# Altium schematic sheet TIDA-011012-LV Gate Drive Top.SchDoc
size 431 x 279 mm; Date: Not shown in title block; ApprovedBy: Not shown in title block; CheckedBy: Not shown in title block; Author: Not shown in title block; CompanyName: Not shown in title block; Engineer: Not shown in title block; Organization: Not shown in title block; Address1: Not shown in title block; Address2: Not shown in title block; Address3: Not shown in title block; Address4: Not shown in title block; DocumentNumber: 1; Revision: Use project parameter SCH_Rev; SheetNumber: 1; SheetTotal: 1; PageSetup: Record=PageOptions¦CenterHorizontal=True¦CenterVertical=True¦PrintScale=1.00¦XCorrection=1.00¦YCorrection=1.00¦PrintKind=0¦BorderSize=5000000¦LeftOffset=0¦BottomOffset=0¦Orientation=2¦PaperLength=1000¦PaperWidth=1000¦Scale=100¦PaperSource=15¦PrintQuality=600¦MediaType=1¦DitherType=10¦PaperKind=Letter¦PrintScaleMode=1
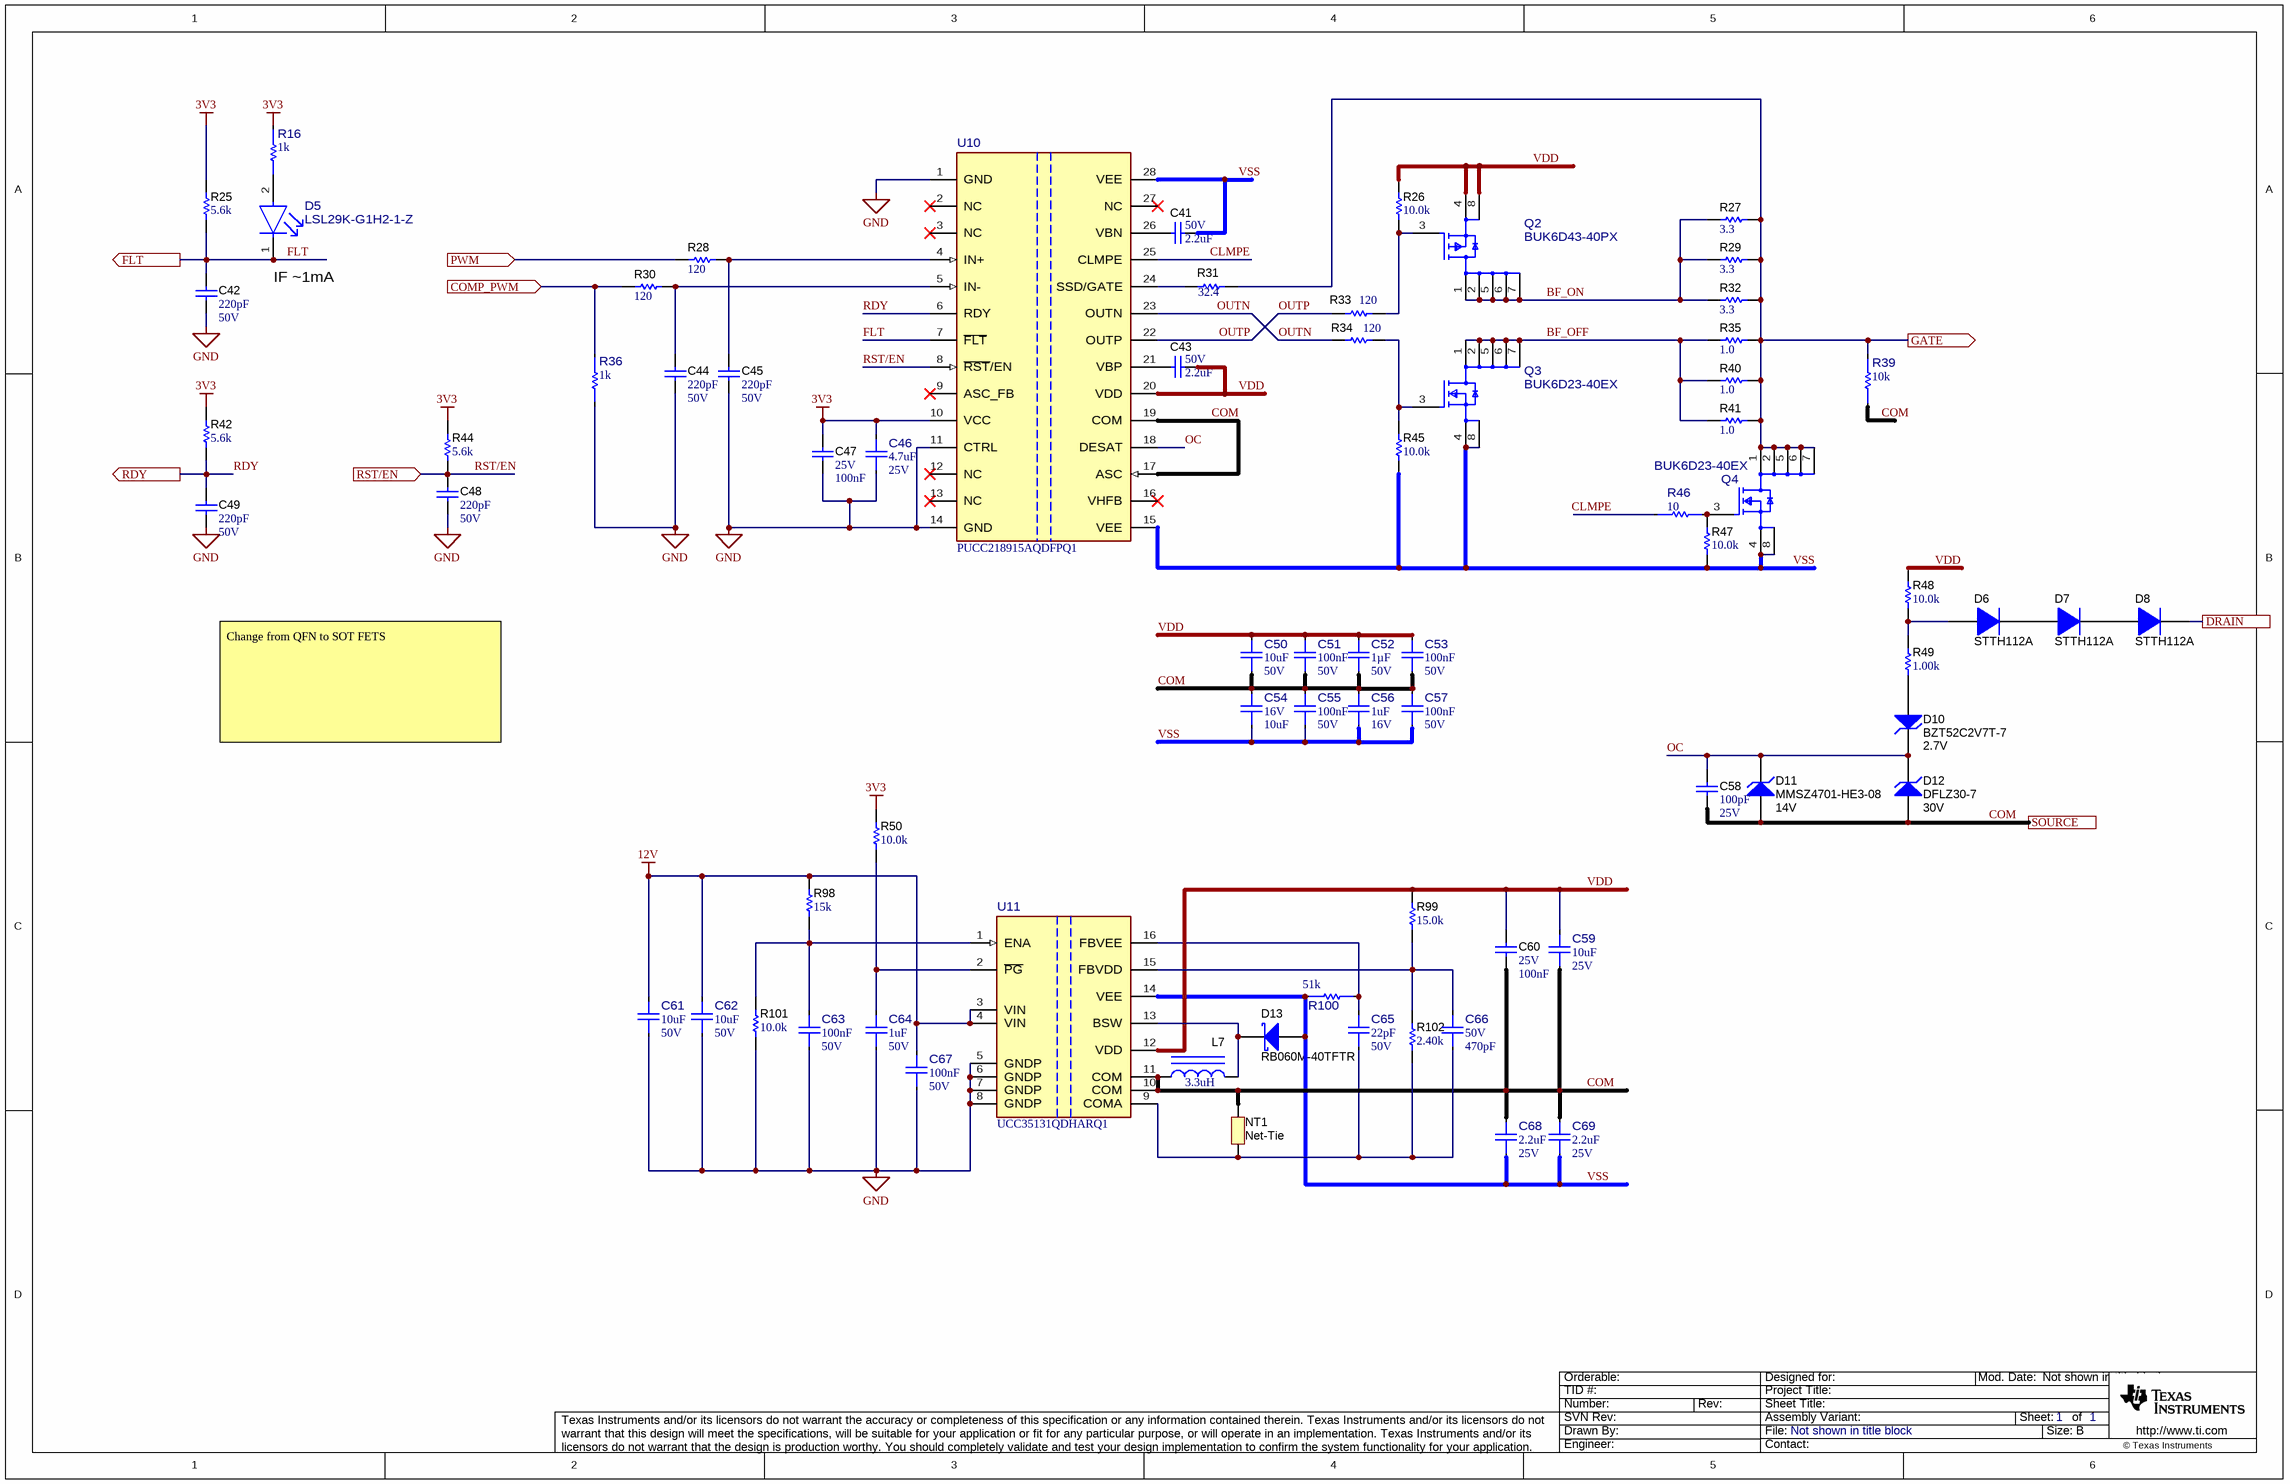
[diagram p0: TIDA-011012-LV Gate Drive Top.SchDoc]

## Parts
C41  VDC_V: 50V  ValueDisplayed: 2.2uF  [0603]  (hidden comment: GRT188R61H225KE13D)
C42  Cap_F: 220pF  VDC_V: 50V  [0603]  (hidden comment: C0603C221K5RACTU)
C43  VDC_V: 50V  ValueDisplayed: 2.2uF  [0603]  (hidden comment: GRT188R61H225KE13D)
C44  Cap_F: 220pF  VDC_V: 50V  [0603]  (hidden comment: C0603C221K5RACTU)
C45  Cap_F: 220pF  VDC_V: 50V  [0603]  (hidden comment: C0603C221K5RACTU)
C46  ValueDisplayed: 4.7uF  VDC_V: 25V  [FP-GRM188R61E475KE15D_0603-MFG]  (hidden comment: GRM188R61E475KE15D)
C47  VDC_V: 25V  Cap_F: 100nF  [0603]  (hidden comment: GCM188R71E104KA57D)
C48  Cap_F: 220pF  VDC_V: 50V  [0603]  (hidden comment: C0603C221K5RACTU)
C49  Cap_F: 220pF  VDC_V: 50V  [0603]  (hidden comment: C0603C221K5RACTU)
C50  ValueDisplayed: 10uF  VDC_V: 50V  [FP-GMC31X7R106K50NT_1206-MFG]  (hidden comment: GMC31X7R106K50NT)
C51  Cap_F: 100nF  VDC_V: 50V  [FP-C0805C104K5RAC7800_0805-MFG]  (hidden comment: C0805C104K5RAC7800)
C52  Cap_F: 1µF  VDC_V: 50V  [FP-CL10B105KB9VPJC_0603-MFG]  (hidden comment: CL10B105KB9VPJC)
C53  Cap_F: 100nF  VDC_V: 50V  [FP-C0603C104K5RAC3121_0603-MFG]  (hidden comment: C0603C104K5RAC3121)
C54  VDC_V: 16V  ValueDisplayed: 10uF  [FP-C1206C106J4RACAUTO_1206-MFG]  (hidden comment: C1206C106J4RACAUTO)
C55  Cap_F: 100nF  VDC_V: 50V  [FP-C0805C104K5RAC7800_0805-MFG]  (hidden comment: C0805C104K5RAC7800)
C56  ValueDisplayed: 1uF  VDC_V: 16V  [FP-GRM188C71C105KA12D_0603-MFG]  (hidden comment: GRM188C71C105KA12D)
C57  Cap_F: 100nF  VDC_V: 50V  [FP-C0603C104K5RAC3121_0603-MFG]  (hidden comment: C0603C104K5RAC3121)
C58  Cap_F: 100pF  VDC_V: 25V  [0603]  (hidden comment: 06033C101KAT2A)
C59  ValueDisplayed: 10uF  VDC_V: 25V  [FP-KGM31HR71E106KU_1206-MFG]  (hidden comment: KGM31HR71E106KU)
C60  VDC_V: 25V  Cap_F: 100nF  [0603]  (hidden comment: GCM188R71E104KA57D)
C61  ValueDisplayed: 10uF  VDC_V: 50V  [FP-GMC31X7R106K50NT_1206-MFG]  (hidden comment: GMC31X7R106K50NT)
C62  ValueDisplayed: 10uF  VDC_V: 50V  [FP-GMC31X7R106K50NT_1206-MFG]  (hidden comment: GMC31X7R106K50NT)
C63  Cap_F: 100nF  VDC_V: 50V  [FP-KGM15BR71H104JT_0603-MFG]  (hidden comment: KGM15BR71H104JT)
C64  ValueDisplayed: 1uF  VDC_V: 50V  [FP-C1206C105J5RECAUTO_1206-MFG]  (hidden comment: C1206C105J5RECAUTO)
C65  ValueDisplayed: 22pF  VDC_V: 50V  [FP-VJ0603D220JLAAJ32_0603-IPC_C]  (hidden comment: VJ0603D220JLAAJ32)
C66  VDC_V: 50V  ValueDisplayed: 470pF  [FP-C0603X471F5GACTU_0603-MFG]  (hidden comment: C0603X471F5GACTU)
C67  Cap_F: 100nF  VDC_V: 50V  [FP-KGM15BR71H104JT_0603-MFG]  (hidden comment: KGM15BR71H104JT)
C68  ValueDisplayed: 2.2uF  VDC_V: 25V  [FP-GRT188C71E225KE13D_0603-MFG]  (hidden comment: GRT188C71E225KE13D)
C69  ValueDisplayed: 2.2uF  VDC_V: 25V  [FP-CGA5L2X7R1E225K160AA_1206-MFG]  (hidden comment: CGA5L2X7R1E225K160AA)
D5  LSL29K-G1H2-1-Z  [FP-LSL29K-G1H2-1-Z_0603-0]
D6  STTH112A  [SMA]
D7  STTH112A  [SMA]
D8  STTH112A  [SMA]
D10  BZT52C2V7T-7  value 2.7V  [SOD-523]
D11  MMSZ4701-HE3-08  value 14V  [SOD-123]
D12  DFLZ30-7  value 30V  [PowerDI123]
D13  RB060M-40TFTR  [SOD-123]
L7  ValueDisplayed: 3.3uH  [0603]  (hidden comment: AIML-0603-3R3K-T)
NT1  Net-Tie  [Net-Tie_0805_HV_NoOverlay]  (net tie, no BOM)
Q2  BUK6D43-40PX  [FP-BUK6D43-40PX_SOT1220-MFG]
Q3  BUK6D23-40EX  [FP-BUK6D23-40EX_SOT1220-MFG]
Q4  BUK6D23-40EX  [FP-BUK6D23-40EX_SOT1220-MFG]
R16  Res_ohm: 1k  [FP-ERJ-3GEYJ102V_0603-MFG]  (hidden comment: ERJ-3GEYJ102V)
R25  ValueDisplayed: 5.6k  [0603]  (hidden comment: RC0603JR-075K6L)
R26  ValueDisplayed: 10.0k  [0603]  (hidden comment: ERJ-3EKF1002V)
R27  ValueDisplayed: 3.3  [1206]  (hidden comment: CRCW12063R30JNEA)
R28  ValueDisplayed: 120  [0603]  (hidden comment: CRCW0603120RJNEA)
R29  ValueDisplayed: 3.3  [1206]  (hidden comment: CRCW12063R30JNEA)
R30  ValueDisplayed: 120  [0603]  (hidden comment: CRCW0603120RJNEA)
R31  ValueDisplayed: 32.4  [1206]  (hidden comment: CRCW120632R4FKEA)
R32  ValueDisplayed: 3.3  [1206]  (hidden comment: CRCW12063R30JNEA)
R33  ValueDisplayed: 120  [0603]  (hidden comment: RT0603BRD07120RL)
R34  ValueDisplayed: 120  [0603]  (hidden comment: RT0603BRD07120RL)
R35  ValueDisplayed: 1.0  [1206]  (hidden comment: CRM1206-JW-1R0ELF)
R36  Res_ohm: 1k  [FP-ERJ-3GEYJ102V_0603-MFG]  (hidden comment: ERJ-3GEYJ102V)
R39  value 10k  [FP-560112116005_0603-MFG]  (hidden comment: 560112116005)
R40  ValueDisplayed: 1.0  [1206]  (hidden comment: CRM1206-JW-1R0ELF)
R41  ValueDisplayed: 1.0  [1206]  (hidden comment: CRM1206-JW-1R0ELF)
R42  ValueDisplayed: 5.6k  [0603]  (hidden comment: RC0603JR-075K6L)
R44  ValueDisplayed: 5.6k  [0603]  (hidden comment: RC0603JR-075K6L)
R45  ValueDisplayed: 10.0k  [0603]  (hidden comment: ERJ-3EKF1002V)
R46  value 10  [FP-ESR03EZPF10R0_0603-MFG]  (hidden comment: ESR03EZPF10R0)
R47  ValueDisplayed: 10.0k  [0603]  (hidden comment: ERJ-3EKF1002V)
R48  ValueDisplayed: 10.0k  [0603]  (hidden comment: ERJ-3EKF1002V)
R49  ValueDisplayed: 1.00k  [0603]  (hidden comment: ERJ-3EKF1001V)
R50  ValueDisplayed: 10.0k  [0603]  (hidden comment: ERJ-3EKF1002V)
R98  ValueDisplayed: 15k  [0603]  (hidden comment: RC0603JR-0715KL)
R99  ValueDisplayed: 15.0k  [0603]  (hidden comment: RT0603BRD0715KL)
R100  value 51k  [FP-ERA-3AED513V_0603-MFG]  (hidden comment: ERA-3AED513V)
R101  ValueDisplayed: 10.0k  [0603]  (hidden comment: RT0603DRE0710KL)
R102  ValueDisplayed: 2.40k  [0603]  (hidden comment: RT0603DRE072K4L)
U10  PUCC218915AQDFPQ1  [DFP0028A-MFG]
U11  UCC35131QDHARQ1  [DHA0016A-MFG]

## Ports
COMP_PWM (in), DRAIN, FLT (out), GATE (out), PWM (in), RDY (out), RST/EN (in), SOURCE

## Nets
3V3: C46.2 C47.2 R16.1 R25.2 R42.2 R44.2 R50.2 U10.10(VCC)
12V: C61.2 C62.2 C67.2 R98.2 U11.3(VIN) U11.4(VIN)
GND: C42.2 C44.2 C45.2 C46.1 C47.1 C48.2 C49.2 C61.1 C62.1 C63.1 C64.1 C67.1 R36.2 R101.1 U10.1(GND) U10.11(CTRL) U10.14(GND) U11.5(GNDP) U11.6(GNDP) U11.7(GNDP) U11.8(GNDP)
BF_OFF: Q3.1(D) Q3.2(D) Q3.5(D) Q3.6(D) Q3.7(D) R35.1 R40.1 R41.1
BF_ON: Q2.1(D) Q2.2(D) Q2.5(D) Q2.6(D) Q2.7(D) R27.1 R29.1 R32.1
CLMPE: R46.1 U10.25(CLMPE)
COM: C50.1 C51.1 C52.1 C53.1 C54.2 C55.2 C56.2 C57.2 C58.2 C59.1 C60.2 C68.2 C69.2 D11.2(A) D12.2(A) L7.1 NT1.2 R39.1 U10.17(ASC) U10.19(COM) U11.10(COM) U11.11(COM) ; port SOURCE
COMP_PWM: R30.1 R36.1 ; port COMP_PWM
DRAIN: D8.1(K) ; port DRAIN
FLT: C42.1 D5.1(CATHODE) R25.1 U10.7(~{FLT}) ; port FLT
GATE: Q4.1(D) Q4.2(D) Q4.5(D) Q4.6(D) Q4.7(D) R27.2 R29.2 R31.2 R32.2 R35.2 R39.2 R40.2 R41.2 ; port GATE
OC: C58.1 D10.1(K) D11.1(K) D12.1(K) U10.18(DESAT)
OUTN: R34.1 U10.23(OUTN)
OUTP: R33.1 U10.22(OUTP)
PWM: R28.1 ; port PWM
RDY: C49.1 R42.1 U10.6(RDY) ; port RDY
RST/EN: C48.1 R44.1 U10.8(~{RST}/EN) ; port RST/EN
VDD: C43.1 C50.2 C51.2 C52.2 C53.2 C59.2 C60.1 Q2.4(S) Q2.8(S) R26.2 R48.2 R99.2 U10.20(VDD) U11.12(VDD)
VSS: C41.1 C54.1 C55.1 C56.1 C57.1 C68.1 C69.1 D13.2(A) Q3.4(S) Q3.8(S) Q4.4(S) Q4.8(S) R45.1 R47.1 R100.1 U10.15(VEE) U10.28(VEE) U11.14(VEE)
NetC41_2: C41.2 U10.26(VBN)
NetC43_2: C43.2 U10.21(VBP)
NetC44_1: C44.1 R30.2 U10.5(IN-)
NetC45_1: C45.1 R28.2 U10.4(IN+)
NetC63_2: C63.2 R98.1 R101.2 U11.1(ENA)
NetC64_2: C64.2 R50.1 U11.2(~{PG})
NetC65_1: C65.1 C66.1 NT1.1 R102.1 U11.9(COMA)
NetC65_2: C65.2 R100.2 U11.16(FBVEE)
NetC66_2: C66.2 R99.1 R102.2 U11.15(FBVDD)
NetD5_2: D5.2(ANODE) R16.2
NetD6_1: D6.1(K) D7.2(A)
NetD6_2: D6.2(A) R48.1 R49.2
NetD7_1: D7.1(K) D8.2(A)
NetD10_2: D10.2(A) R49.1
NetD13_1: D13.1(K) L7.2 U11.13(BSW)
NetQ2_3: Q2.3(G) R26.1 R33.2
NetQ3_3: Q3.3(G) R34.2 R45.2
NetQ4_3: Q4.3(G) R46.2 R47.2
NetR31_1: R31.1 U10.24(SSD/GATE)

Not connected (* = marked no-connect by the designer): U10 2(NC)* 3(NC)* 9(ASC_FB)* 12(NC)* 13(NC)* 16(VHFB)* 27(NC)*

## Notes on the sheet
- (near D5) IF
  mA
- Change from QFN to SOT FETS

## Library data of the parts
C41 C43 = CMP-0007502-5: CAP, CERM, 2.2 uF, 50 V, +/- 10%, X5R, AEC-Q200 Grade 3, 0603; Manufacturer: MuRata; TaMin_C: -55°C; Polarized: N; SizeAreaWB_mm2: 4.68; Value1: Unknown; U/M: EA; Value: 2.2uF; TaMax_C: 85°C; SizeZ_mm: 1; SizeX_mm: 1.6; SizeY_mm: 0.8; SizeArea_mm2: 1.28; AEC Qualified: Y; Cap_F: 2.2µF; AEC Grade: 3; AEC Category: Q200
C42 C44 C45 C48 C49 = CMP-0006895-4: CAP, CERM, 220 pF, 50 V, +/- 10%, X7R, 0603; Manufacturer: Kemet; TaMin_C: -55°C; Polarized: N; SizeAreaWB_mm2: 4.68; Value1: Unknown; U/M: EA; Value: 220pF; TaMax_C: 125°C; SizeZ_mm: 1; SizeX_mm: 1.6; SizeY_mm: 0.8; SizeArea_mm2: 1.28; AEC Category: Q200
C46 = CMP-0091702-1: 4.7µF ±10% 25V Ceramic Capacitor X5R 0603 (1608 Metric); Manufacturer: Murata; AEC Qualified: No; SizeZ_mm: 1mm; TempCo: 15%
C47 C60 = CMP-0084679-1: CAP, CERM, 0.1 µF, 25 V,+/- 10%, X7R, AEC-Q200 Grade 1, 0603; Manufacturer: MuRata; TaMin_C: -55°C; SizeY_mm: 0.8; Polarized: N; SizeArea_mm2: 1.28; SizeZ_mm: 1; SizeX_mm: 1.6; AEC Qualified: Y; AEC Category: Q200; Value: 0.1uF; ValueDisplayed: 0.1µF; TaMax_C: 125°C; U/M: EA; SizeAreaWB_mm2: 4.68
C50 C61 C62 = CMP-0093201-1: 10 µF ±10% 50V Ceramic Capacitor X7R 1206 (3216 Metric); Manufacturer: Cal-Chip Electronics; AEC Qualified: No; SizeZ_mm: 1.8mm; TempCo: 15%; Value: 10µF
C51 C55 = CMP-0120154-1: 0.1 µF ±10% 50V Ceramic Capacitor X7R 0805 (2012 Metric); Manufacturer: KEMET; AEC Qualified: No; SizeZ_mm: 0.88mm; TempCo: 15%; ValueDisplayed: 0.1uF; Value: 100nF
C52 = CMP-0122257-1: 1 µF ±10% 50V Ceramic Capacitor X7R 0603 (1608 Metric); Manufacturer: Samsung; AEC Grade: Grade 1; AEC Qualified: Yes; SizeZ_mm: 1mm; TempCo: 15%; ValueDisplayed: 1uF; Value: 1µF
C53 C57 = CMP-0093594-1: 0.1 µF ±10% 50V Ceramic Capacitor X7R 0603 (1608 Metric); Manufacturer: KEMET; AEC Grade: Grade 1; AEC Qualified: Yes; ValueDisplayed: 0.1uF; SizeZ_mm: 0.87mm; TempCo: 15%; Value: 100nF
C54 = CMP-0094514-1: 10 µF ±5% 16V Ceramic Capacitor X7R 1206 (3216 Metric); Manufacturer: KEMET; SizeZ_mm: 1.8mm; TempCo: 15%; Cap_F: 10µF; Value: 10µF; AEC Qualified: Yes; AEC Grade: Grade 1
C56 = CMP-0122429-1: 1 µF ±10% 16V Ceramic Capacitor X7S 0603 (1608 Metric); Manufacturer: Murata; AEC Qualified: No; Cap_F: 1µF; SizeZ_mm: 0.9mm; TempCo: 22%; Value: 1µF
C58 = CMP-0006751-4: CAP, CERM, 100 pF, 25 V, +/- 10%, X7R, 0603; Manufacturer: AVX; TaMin_C: -55°C; Polarized: N; SizeAreaWB_mm2: 4.68; Value1: Unknown; U/M: EA; Value: 100pF; TaMax_C: 125°C; SizeZ_mm: 1; SizeX_mm: 1.6; SizeY_mm: 0.8; SizeArea_mm2: 1.28; AEC Category: Q200
C59 = CMP-0044202-1: 10 µF ±10% 25V Ceramic Capacitor X7R 1206 (3216 Metric); Manufacturer: KYOCERA AVX; AEC Qualified: No; Cap_F: 10µF; SizeZ_mm: 1.9mm; TempCo: 15%; Value: 10µF
C63 C67 = CMP-0120061-1: 0.1 µF ±5% 50V Ceramic Capacitor X7R 0603 (1608 Metric); Manufacturer: KYOCERA AVX; AEC Qualified: No; SizeZ_mm: 0.94mm; TempCo: 15%; ValueDisplayed: 0.1uF; Value: 100nF
C64 = CMP-0094524-1: 1 µF ±5% 50V Ceramic Capacitor X7R 1206 (3216 Metric); Manufacturer: KEMET; TempCo: 15%; Cap_F: 1µF; AEC Grade: Grade 1; AEC Qualified: Yes; SizeZ_mm: 1.1mm; Value: 1µF
C65 = CMP-0039814-1: 22 pF ±5% 50V Ceramic Capacitor C0G, NP0 0603 (1608 Metric); Manufacturer: Vishay; AEC Grade: Grade 0; AEC Qualified: Yes; SizeZ_mm: 0.97mm; TempCo: 30ppm/°C; Value: 22pF
C66 = CMP-0097612-1: Cap Ceramic 470pF 50V C0G 1% SMD 0603 125°C Paper T/R; Manufacturer: KEMET; SizeZ_mm: 0.95mm; TempCo: 30ppm/°C; AEC Qualified: No
C68 = CMP-0125378-1: Multi-Layer Ceramic Capacitor 2.2uF 25V X7S ±10% 0603 Paper T/R; Manufacturer: Murata; AEC Grade: Grade 1; AEC Qualified: Yes; Cap_F: 2.2µF; SizeZ_mm: 1mm; TempCo: 22%; Value: 2.2µF
C69 = CMP-0090741-1: Cap Ceramic 2.2uF 25V X7R 10% Pad SMD 1206 +125°C Automotive T/R; Manufacturer: TDK; Cap_F: 2.2µF; Value: 2.2µF; Tolerance_%: 0.1%; TempCo: 15%; AEC Grade: Grade 1; AEC Qualified: Yes; SizeZ_mm: 1.9mm
D5 = CMP-0092845-1: LED Uni-Color Red 643nm 2-Pin Chip 0603(1608Metric) T/R; Manufacturer: OSRAM Opto Semiconductors; AEC Grade: Grade 2; LuminousFlux_PhiV: 8.1/16.1lm; Vf_V: 1.8V; Forward Current: 2mA; Led Orientation: Top View; SizeZ_mm: 0.67mm; AEC Qualified: Yes; Luminous Intensity: 1.8-2.24/3.55-4.5mcd; Vr_V: 12V; Angle: 160°; LambdaD: 630nm; Tjmax_C: 110°C
D6-D8 = CMP-0077081-2: Diode, Ultrafast, 1200 V, 1 A, SMA; Manufacturer: STMicroelectronics; AEC Qualified: N; TJmax_C: 175°C; SizeX_mm: 5.59; Green_Lifecycle: Not Set; Io_A: 1A; Value2: 1.9V; SizeY_mm: 2.92; SizeZ_mm: 2.87; AEC Category: Q101; Value: 1200V; SizeAreaWB_mm2: 37.3428; Vr_V: 1.2kV; Green_REACh: Incomplete; SizeArea_mm2: 16.3228
D10 = CMP-0005892-4: Diode, Zener, 2.7 V, 300 mW, SOD-523; Manufacturer: Diodes Inc.; SizeY_mm: 0.9; AEC Category: Q101; SizeX_mm: 1.7; Power_W: 300mW; Value1: 0.3W; SizeZ_mm: 0.65; SizeAreaWB_mm2: 5.13; RJA_CperW: 417; SizeArea_mm2: 1.53
D11 = CMP-0077574-3: Diode, Zener, 14 V, 500 mW, AEC-Q101, SOD-123; Manufacturer: Vishay-Semiconductor; Power_W: 500mW; Value1: 0.5W; AEC Qualified: Y; SizeZ_mm: 1.35; SizeAreaWB_mm2: 13.095; SizeX_mm: 3.85; AEC Category: Q101; RJA_CperW: 340; SizeY_mm: 1.7; SizeArea_mm2: 6.545
D12 = CMP-0005417-4: Diode, Zener, 30 V, 1 W, PowerDI123; Manufacturer: Diodes Inc.; SizeX_mm: 3.7; Power_W: 1W; SizeY_mm: 1.78; AEC Category: Q101; RJA_CperW: 110; SizeArea_mm2: 6.586; SizeZ_mm: 0.98; SizeAreaWB_mm2: 13.066
D13 = CMP-0028628-2: Diode, Schottky, 40 V, 2 A, SOD-123; Manufacturer: Rohm; Green_REACh: Incomplete; SizeX_mm: 3.85; SizeZ_mm: 1.35; TJmax_C: 150°C; Value1: 2A; SizeAreaWB_mm2: 13.095; SizeArea_mm2: 6.545; AEC Category: Q101; Value2: 0.56V; SizeY_mm: 1.7; Value: 40V; Vf_V: 560mV; Green_Lifecycle: Not Set
L7 = CMP-0059575-1: Inductor, Multilayer, Ferrite, 3.3 uH, 0.015 A, 1.55 ohm, SMD; Manufacturer: Abracon Corporation; Green_Lifecycle: Active; SizeAreaWB_mm2: 4.68; DCR_ohm: 1.55; Green_REACh: Passed; Value: 3.3uH; Imax_A: 15mA; SizeZ_mm: 1; SizeX_mm: 1.6; SizeY_mm: 0.8; Value2: 0.015A; SizeArea_mm2: 1.28; Ind_H: 3.3µH; AEC Qualified: N; AEC Category: Q200
NT1 = CMP-0078142-6: Single point connection between nets.
Q2 = CMP-0120257-1: P-Channel 40 V 6A (Ta) 15W (Tc) Surface Mount DFN2020MD-6; Manufacturer: Nexperia; AEC Qualified: Yes; IdsMax_A: -6A; QgTyp_nC: 24nC @ -10V; Rdson45_ohm: 30m; SizeZ_mm: 0.65mm; VdsMax_V: -1.2V; Vgs_V: 20V; ChMode: False; AEC Grade: Grade 0; Drain To Source Breakdown Voltage: -40V; Input Capacitace At Vds: 1260pF @ -20V; Number Of Channels: 1; Power_W: 2.3W; Pulse Drain Current: -56A; Reverse Recovery Charge: 8nC; Reverse Recovery Time: 15.6ns; Rthja Max: 57K/W; TaMax_C: +175°C; TaMin_C: -55°C; Threshold Vgs Max: -2.7V; Threshold Vgs Min: -1.4V; Transconductance: 33S; Turn Off Delay Time: 35ns; Turn On Delay Time: 9ns; Typ Forward Diode Voltage: -0.8V
Q3 Q4 = CMP-0120256-1: N-Channel 40 V 8A (Ta), 19A (Tc) 2.3W (Ta), 15W (Tc) Surface Mount DFN2020MD-6; Manufacturer: Nexperia; AEC Qualified: Yes; QgTyp_nC: 11nC @ 10V; Rdson45_ohm: 17m; SizeZ_mm: 0.65mm; VdsMax_V: 1.2V; Vgs_V: 20V; ChMode: False; AEC Grade: Grade 0; Drain To Source Breakdown Voltage: 40V; Input Capacitace At Vds: 582pF @ 20V; Number Of Channels: 1; Pulse Drain Current: 76A; Reverse Recovery Charge: 5.4nC; Reverse Recovery Time: 12.8ns; Rthja Max: 57K/W; TaMax_C: +175°C; TaMin_C: -55°C; Threshold Vgs Max: 2.7V; Threshold Vgs Min: 1.3V; Transconductance: 33S; Turn Off Delay Time: 12ns; Turn On Delay Time: 2ns; Typ Forward Diode Voltage: 0.8V
R16 R36 = CMP-0089144-1: 1 kOhms ±5% 0.1W, 1/10W Chip Resistor 0603 (1608 Metric) Automotive AEC-Q200 Thick Film; Manufacturer: Panasonic; Power_W: 100mW; AEC Qualified: Yes; Voltage: 75V; AEC Grade: Grade 0; SizeZ_mm: 0.55mm; TempCo: 200ppm/°C
R25 R42 R44 = CMP-0025933-5: RES, 5.6 k, 5%, 0.1 W, 0603; Manufacturer: Yageo; Power_W: 100mW; TempCo: 100 ppm/C; Value_Code: 5k60; Value: 5.6k; EIA_Code: E24; SizeX_mm: 1.6; SizeY_mm: 0.8; SizeZ_mm: 1; Value2: 0.1W; SizeArea_mm2: 1.28; AEC Qualified: N; VDC_V: 75V; AEC Category: Q200; SizeAreaWB_mm2: 4.68
R26 R45 R47 R48 R50 = CMP-0022684-3: RES, 10.0 k, 1%, 0.1 W, 0603; Manufacturer: Panasonic; Power_W: 100mW; TempCo: 100 ppm/C; Value_Code: 10k0; U/M: EA; Value: 10.0k; EIA_Code: E96; Res_ohm: 10k; SizeX_mm: 1.6; SizeY_mm: 0.8; SizeZ_mm: 1; Value2: 0.1W; SizeArea_mm2: 1.28; VDC_V: 75V; AEC Category: Q200
R27 R29 R32 = CMP-0018677-3: RES, 3.3, 5%, 0.25 W, AEC-Q200 Grade 0, 1206; Manufacturer: Vishay-Dale; Power_W: 250mW; TempCo: 200 ppm/C; Value_Code: 3R30; Value: 3.3; EIA_Code: E24; SizeX_mm: 3.2; SizeY_mm: 1.6; SizeZ_mm: 1.35; Value2: 0.25W; SizeArea_mm2: 5.12; AEC Qualified: Y; VDC_V: 200V; AEC Category: Q200; AEC Grade: 0
R28 R30 = CMP-0025710-4: RES, 120, 5%, 0.1 W, AEC-Q200 Grade 0, 0603; Manufacturer: Vishay-Dale; Power_W: 100mW; TempCo: 200 ppm/C; Value_Code: 120R; Value: 120; EIA_Code: E24; SizeX_mm: 1.6; SizeY_mm: 0.8; SizeZ_mm: 1; Value2: 0.1W; SizeArea_mm2: 1.28; AEC Qualified: Y; VDC_V: 75V; AEC Category: Q200; AEC Grade: 0
R31 = CMP-0016910-3: RES, 32.4, 1%, 0.25 W, AEC-Q200 Grade 0, 1206; Manufacturer: Vishay-Dale; Power_W: 250mW; TempCo: 100 ppm/C; Value_Code: 32R4; Value: 32.4; EIA_Code: E96; SizeX_mm: 3.2; SizeY_mm: 1.6; SizeZ_mm: 1.35; Value2: 0.25W; SizeArea_mm2: 5.12; AEC Qualified: Y; VDC_V: 200V; AEC Category: Q200; AEC Grade: 0
R33 R34 = CMP-0023691-3: RES, 120, 0.1%, 0.1 W, 0603; Manufacturer: Yageo America; Power_W: 100mW; TempCo: 25 ppm/C; Value_Code: 120R; U/M: EA; Value: 120; EIA_Code: E192; SizeX_mm: 1.6; SizeY_mm: 0.8; SizeZ_mm: 1; Value2: 0.1W; SizeArea_mm2: 1.28; VDC_V: 75V; AEC Category: Q200
R35 R40 R41 = CMP-0018745-2: RES, 1.0, 5%, 0.5 W, 1206; Manufacturer: Bourns; Power_W: 500mW; TempCo: 150 ppm/C; Value_Code: 1R00; U/M: EA; Value: 1.0; EIA_Code: E24; Res_ohm: 1; SizeX_mm: 3.2; SizeY_mm: 1.6; SizeZ_mm: 1.35; Value2: 0.5W; SizeArea_mm2: 5.12; VDC_V: 1V; AEC Category: Q200
R39 = CMP-0125815-1: 10 kOhms ±1% 0.1W, 1/10W Chip Resistor 0603 (1608 Metric) Anti-Sulfur Thick Film; Manufacturer: Wurth Electronics; AEC Qualified: No; Power_W: 100mW; SizeZ_mm: 0.6mm; TempCo: 100ppm/°C; VDC_V: 75V
R46 = CMP-0094841-1: 10 Ohms ±1% 0.25W, 1/4W Chip Resistor 0603 (1608 Metric) Automotive AEC-Q200, Pulse Withstanding Thick Film; Manufacturer: ROHM; AEC Qualified: Yes; SizeZ_mm: 0.55mm; TempCo: 100ppm/°C; AEC Grade: Grade 0; Power_W: 250mW; VDC_V: 150V
R49 = CMP-0022680-4: RES, 1.00 k, 1%, 0.1 W, 0603; Manufacturer: Panasonic; Power_W: 100mW; TempCo: 100 ppm/C; Value_Code: 1k00; U/M: EA; Value: 1.00k; EIA_Code: E96; Res_ohm: 1k; SizeX_mm: 1.6; SizeY_mm: 0.8; SizeZ_mm: 1; SizeArea_mm2: 1.28; VDC_V: 75V; AEC Category: Q200; Value2: 0.1W
R98 = CMP-0025890-5: RES, 15 k, 5%, 0.1 W, 0603; Manufacturer: Yageo; Power_W: 100mW; TempCo: 100 ppm/C; Value_Code: 15k0; Value: 15k; EIA_Code: E24; SizeX_mm: 1.6; SizeY_mm: 0.8; SizeZ_mm: 1; Value2: 0.1W; SizeArea_mm2: 1.28; AEC Qualified: N; VDC_V: 75V; AEC Category: Q200; SizeAreaWB_mm2: 4.68
R99 = CMP-0023780-3: RES, 15.0 k, 0.1%, 0.1 W, 0603; Manufacturer: Yageo America; Power_W: 100mW; TempCo: 25 ppm/C; Value_Code: 15k0; U/M: EA; Value: 15.0k; EIA_Code: E192; Res_ohm: 15k; SizeX_mm: 1.6; SizeY_mm: 0.8; SizeZ_mm: 1; Value2: 0.1W; SizeArea_mm2: 1.28; VDC_V: 75V; AEC Category: Q200
R100 = CMP-0031881-1: 51 kOhms ±0.5% 0.1W, 1/10W Chip Resistor 0603 (1608 Metric) Automotive AEC-Q200 Thin Film; Manufacturer: Panasonic; AEC Grade: Grade 0; AEC Qualified: Yes; Power_W: 100mW; SizeZ_mm: 0.55mm; TempCo: 25ppm/°C; VDC_V: 75V
R101 = CMP-0024586-3: RES, 10.0 k, 0.5%, 0.1 W, 0603; Manufacturer: Yageo America; Power_W: 100mW; TempCo: 50 ppm/C; Value_Code: 10k0; U/M: EA; Value: 10.0k; EIA_Code: E192; Res_ohm: 10k; SizeX_mm: 1.6; SizeY_mm: 0.8; SizeZ_mm: 1; Value2: 0.1W; SizeArea_mm2: 1.28; VDC_V: 75V; AEC Category: Q200
R102 = CMP-0025064-3: RES, 2.40 k, 0.5%, 0.1 W, 0603; Manufacturer: Yageo America; Power_W: 100mW; TempCo: 50 ppm/C; Value_Code: 2k40; U/M: EA; Value: 2.40k; EIA_Code: E192; Res_ohm: 2.4k; SizeX_mm: 1.6; SizeY_mm: 0.8; SizeZ_mm: 1; Value2: 0.1W; SizeArea_mm2: 1.28; VDC_V: 75V; AEC Category: Q200
U10 = CMP-0128293-1: Single Channel Isolated Pre-Driver for SiC/IGBT with Active Protection; Manufacturer: Texas Instruments; SizeZ_mm: 2.6mm; AEC Qualified: Yes; AEC Grade: Grade 1; Max Supply Voltage: 28V; Min Supply Voltage: 3V; Number Of Drivers: 1; Standoff Height: 0.05mm; TaMax_C: +125°C; TaMin_C: -40°C; TJmax_C: +150°C; Turn Off Delay Time: 65ns
U11 = CMP-0126653-2: Automotive 2.0W, 12V VIN, High-Density, > 5kVRMS, Isolated DC/DC Module; Manufacturer: Texas Instruments; SizeZ_mm: 2.6mm; AEC Qualified: Yes; AEC Grade: Grade 1; Max Supply Voltage: 20V; Min Supply Voltage: 5.5V; Number Of Outputs: 2; Output Type: AdjustableProgrammable; Output Voltage: -2-8/12-18V; Standoff Height: 0.1mm; TaMax_C: +125°C; TaMin_C: -40°C; TJmax_C: +150°C; AEC Category: Q200; CompType: IC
